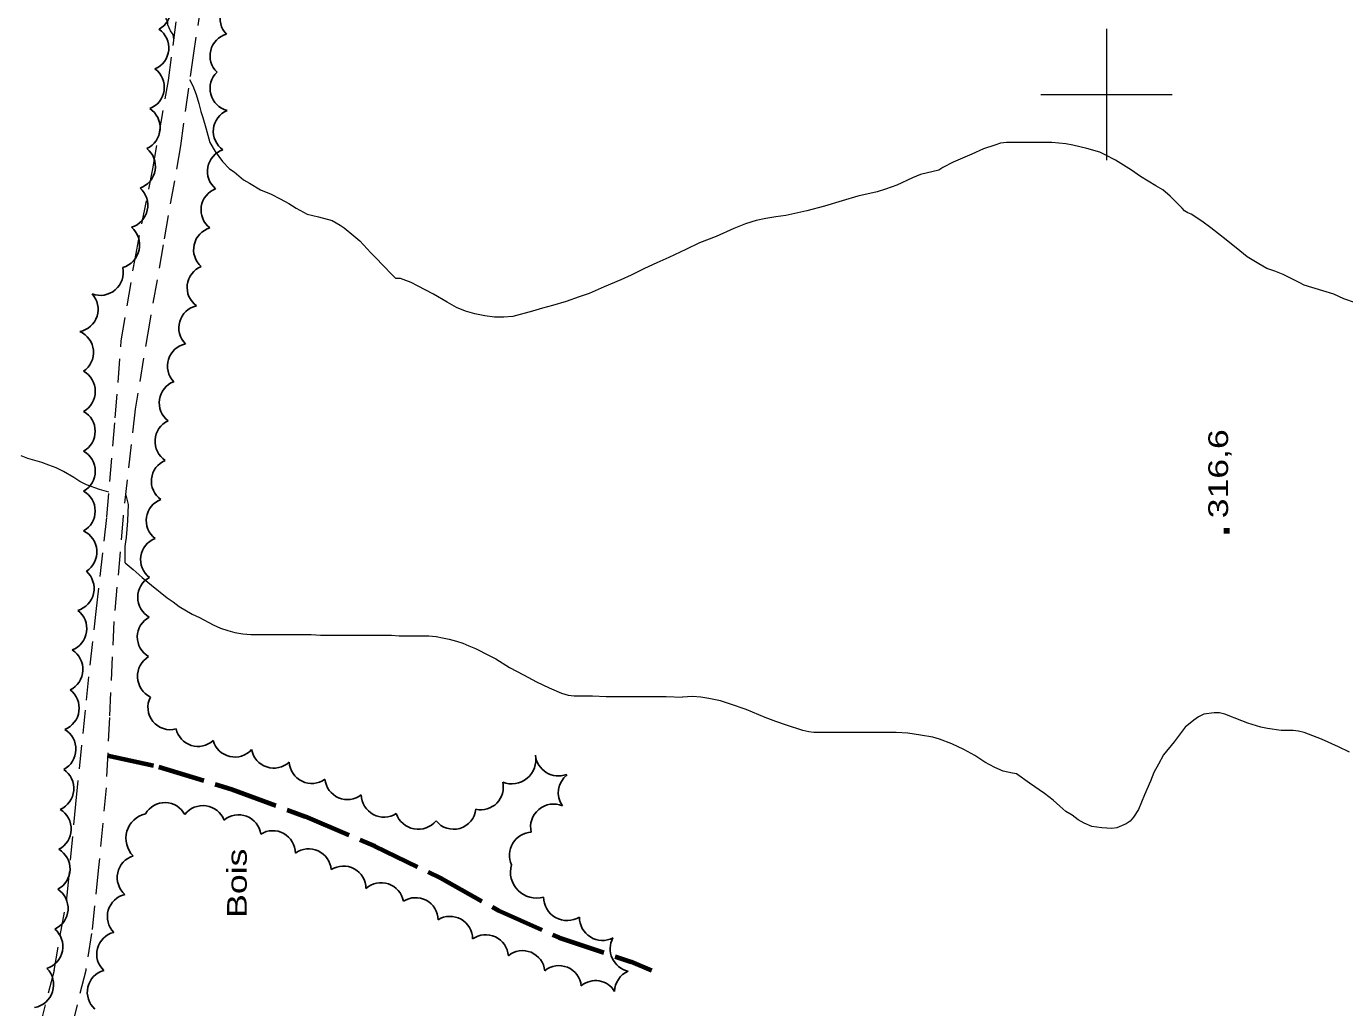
# Model space of a CAD drawing. Extents: x 240591 to 242335, y 5323482 to 5326937.
# Drawn here: x 240835.7 to 241036.2, y 5324261 to 5324410.4 of the extents above; entities that cross this region are included whole.
import ezdxf

# ---------------------------------------------------------------- set-up
doc = ezdxf.new("R2010")
doc.units = 0
doc.header["$LTSCALE"] = 1.2
doc.linetypes.add('LONG_DASHED', pattern=[7.5, 6, -1.5])
doc.linetypes.add('MEDIUM_DASHED', pattern=[4.5, 3, -1.5])
for name, color, linetype, lineweight in [('19', 7, 'Continuous', 13), ('2', 7, 'Continuous', 13), ('22', 7, 'LONG_DASHED', 70), ('3', 7, 'Continuous', 140), ('44', 7, 'Continuous', 25), ('61', 7, 'Continuous', 13)]:
    doc.layers.add(name, color=color, linetype=linetype, lineweight=lineweight)

msp = doc.modelspace()

# ---------------------------------------------------------------- linework, layer by layer
at = {"layer": '19', "linetype": 'MEDIUM_DASHED'}
for points in [[(240863.1, 5324419.4), (240861.1, 5324406.3), (240859.1, 5324392.2), (240856.5, 5324377.1), (240854.4, 5324365.2), (240852.2, 5324352.1), (240850.4, 5324335.8), (240849, 5324319.8), (240848.3, 5324305.2), (240847.8, 5324294.5), (240846.6, 5324281.9), (240845.6, 5324272.3), (240844.7, 5324266.7)], [(240839.9, 5324266.7), (240841.9, 5324278.1), (240843.2, 5324292), (240844.8, 5324307.8), (240846.3, 5324321.3), (240847.9, 5324335.7), (240849.2, 5324350.8), (240850.1, 5324362.5), (240852.2, 5324375), (240854.9, 5324388.7), (240857.3, 5324402.1), (240859.2, 5324416.9)], [(240839.9, 5324266.7), (240835.6, 5324250.1), (240830.7, 5324233.1), (240825.3, 5324215.3), (240819.4, 5324197.9), (240814.4, 5324181.3), (240809.9, 5324167.7), (240807.2, 5324159.7), (240806.2, 5324153.6), (240799.6, 5324150.5), (240789.6, 5324140.4), (240781.9, 5324131), (240772.8, 5324120.8), (240762.9, 5324110.8)], [(240844.7, 5324266.7), (240842.2, 5324256.7), (240839.1, 5324248.6), (240835.3, 5324236.2), (240830.5, 5324219.5), (240824.6, 5324201.3), (240820.2, 5324186.8), (240816.1, 5324172.5)]]:
    msp.add_lwpolyline(points, dxfattribs=at)
at = {"layer": '2'}
for points in [[(240858.1, 5324408.4), (240858, 5324409.1), (240857.6, 5324409.7), (240857.2, 5324410.6), (240857.2, 5324411.1), (240856.9, 5324411.6)], [(240848.2, 5324339.5), (240846.8, 5324339.9), (240844.8, 5324340.6), (240843.8, 5324341.1), (240842.9, 5324341.7), (240841.3, 5324342.6), (240840.2, 5324343.2), (240839.1, 5324343.6), (240838, 5324344), (240835.9, 5324344.6)], [(240850.7, 5324328.7), (240850.7, 5324331.2), (240850.8, 5324331.9), (240850.9, 5324332.6), (240851.1, 5324335.1), (240851.2, 5324337.6), (240850.8, 5324339.2)]]:
    msp.add_lwpolyline(points, dxfattribs=at)
at = {"layer": '2', "linetype": 'LONG_DASHED'}
for points in [[(240860.5, 5324402.3), (240861, 5324401.3), (240861.5, 5324400), (240861.9, 5324398.6), (240862.2, 5324397.4), (240862.5, 5324396.5), (240863, 5324394.9), (240863.3, 5324393.8), (240863.6, 5324392.7), (240864.4, 5324391.3), (240865.5, 5324389.8), (240866.6, 5324388.7), (240867.3, 5324388.2), (240868.7, 5324387), (240869.6, 5324386.5), (240871.3, 5324385.5), (240872.9, 5324384.8), (240874.3, 5324384.1), (240875.6, 5324383.4), (240876.7, 5324382.7), (240878.4, 5324381.8), (240880.1, 5324381.4), (240882.2, 5324380.8), (240883.4, 5324380.1), (240884, 5324379.7), (240885.5, 5324378.5), (240886.4, 5324377.7), (240888.1, 5324375.9), (240889, 5324375), (240889.8, 5324374.1), (240891.5, 5324372.4), (240891.9, 5324372)], [(240991.7, 5324392.7), (240990.7, 5324392.7), (240988, 5324392.7), (240984.8, 5324392.7), (240983.9, 5324392.6), (240983, 5324392.3), (240981.3, 5324391.7), (240979.5, 5324390.9), (240976.7, 5324389.7), (240975.1, 5324388.9), (240974.5, 5324388.5)], [(241037.9, 5324368.3), (241036.1, 5324368.9), (241034.6, 5324369.6), (241032.9, 5324370.1), (241030.1, 5324371), (241029.3, 5324371.4), (241026.9, 5324372.6), (241025.6, 5324373.1), (241024.4, 5324373.5), (241023.2, 5324374.2), (241021.4, 5324375.3), (241020.3, 5324376.2), (241018.2, 5324377.9), (241015.9, 5324379.7), (241014.5, 5324380.7), (241012.9, 5324381.8), (241012.4, 5324382), (241011.9, 5324382.3), (241011.5, 5324382.7), (241009.7, 5324384.5), (241008.6, 5324385.5), (241007.5, 5324386.1), (241005.2, 5324387.5), (241003.8, 5324388.5), (241001.4, 5324390), (240999.8, 5324390.8), (240999, 5324391.2), (240997, 5324391.8), (240994.9, 5324392.3), (240993.8, 5324392.5), (240991.7, 5324392.7)], [(240974.5, 5324388.5), (240971.7, 5324387.8), (240970.5, 5324387.3), (240968.1, 5324386.2), (240966.4, 5324385.6), (240965.1, 5324385.2), (240962.2, 5324384.5), (240959.8, 5324383.8), (240957.1, 5324383), (240954.4, 5324382.3), (240951.2, 5324381.6), (240949.7, 5324381.4), (240948.2, 5324381.1), (240946.7, 5324380.8), (240945.1, 5324380.3), (240943.3, 5324379.6), (240940.6, 5324378.4), (240938.1, 5324377.4), (240936, 5324376.4), (240933.4, 5324375.2), (240931.6, 5324374.4), (240929.7, 5324373.5), (240927.7, 5324372.5), (240926.1, 5324371.8), (240923.6, 5324370.7), (240921.3, 5324369.7), (240919.8, 5324369.2), (240917.8, 5324368.5), (240915.7, 5324367.9), (240914.2, 5324367.5), (240912.7, 5324367), (240909.7, 5324366.2), (240908.3, 5324366.1), (240906.9, 5324366.1), (240905.4, 5324366.3), (240903.9, 5324366.6), (240902.5, 5324367), (240901.1, 5324367.6), (240899.7, 5324368.4), (240897.6, 5324369.6), (240895.2, 5324370.9), (240894.2, 5324371.4), (240892.6, 5324372), (240891.9, 5324372)], [(240835.9, 5324344.6), (240834.9, 5324345)], [(240850.7, 5324328.7), (240850.7, 5324328.7), (240851.9, 5324327.7), (240853.3, 5324326.5), (240854.7, 5324325.3), (240857.1, 5324323.4), (240858, 5324322.8), (240858.9, 5324322.1), (240860.9, 5324320.9), (240862, 5324320.4), (240864.1, 5324319.3), (240865.2, 5324318.8), (240866.3, 5324318.4), (240867.4, 5324318.1), (240868.6, 5324317.9), (240869.8, 5324317.8), (240871, 5324317.8), (240872.3, 5324317.8), (240873.6, 5324317.8), (240874.9, 5324317.8), (240876.2, 5324317.8), (240877.6, 5324317.8), (240879, 5324317.8), (240880.4, 5324317.7), (240881.7, 5324317.7), (240883.1, 5324317.7), (240884.5, 5324317.7), (240885.8, 5324317.7), (240887.2, 5324317.7), (240888.5, 5324317.7), (240889.9, 5324317.7), (240891.2, 5324317.7), (240892.4, 5324317.6), (240894.8, 5324317.6), (240896.9, 5324317.6), (240898, 5324317.5), (240899, 5324317.3), (240900, 5324317.1), (240901.1, 5324316.8), (240902.1, 5324316.5), (240903, 5324316.1), (240904, 5324315.7), (240906.1, 5324314.6), (240907.1, 5324314.1), (240909.2, 5324312.8), (240911.3, 5324311.7), (240913.3, 5324310.6), (240915.2, 5324309.7), (240917.1, 5324308.9), (240918.1, 5324308.6), (240919, 5324308.5), (240920, 5324308.5), (240921.8, 5324308.5), (240923.9, 5324308.4), (240926.1, 5324308.4), (240928.3, 5324308.4), (240930.6, 5324308.4), (240933, 5324308.4), (240935.5, 5324308.3)], [(240948.1, 5324305.2), (240945.2, 5324306.4), (240942.8, 5324307.2), (240941.3, 5324307.7), (240939.5, 5324308.1), (240938.3, 5324308.3), (240937, 5324308.4), (240935.5, 5324308.3)], [(241037, 5324299.9), (241035.3, 5324300.7), (241032.7, 5324301.9), (241030.1, 5324302.9), (241029.2, 5324303.1), (241028.4, 5324303.2), (241026.6, 5324303.2), (241024.5, 5324303.5), (241023.5, 5324303.7), (241021.5, 5324304.3), (241020.6, 5324304.7), (241018, 5324305.7), (241017.2, 5324305.9), (241016.4, 5324305.9), (241014.8, 5324305.7), (241014, 5324305.3), (241013.3, 5324304.8), (241012, 5324303.7), (241011.5, 5324303.1), (241010.3, 5324301.5), (241008.7, 5324299.5), (241007.9, 5324298.1), (241007.2, 5324296.8), (241006.7, 5324295.5), (241005.8, 5324293.4), (241004.9, 5324291.2), (241004.1, 5324290), (241003.6, 5324289.4), (241003, 5324289), (241001.6, 5324288.4), (241000.8, 5324288.3), (240999.3, 5324288.4), (240997.8, 5324288.6), (240996.6, 5324289.1), (240995.7, 5324289.6), (240994.8, 5324290.3), (240993.8, 5324290.9), (240992.9, 5324291.7), (240991.9, 5324292.6), (240990.6, 5324293.6), (240988.3, 5324295.2), (240986.3, 5324296.6), (240985.7, 5324296.7), (240984.3, 5324297), (240983, 5324297.6), (240981.5, 5324298.4), (240980, 5324299.4), (240978.3, 5324300.3), (240976.5, 5324301.2), (240974.6, 5324301.9), (240973.6, 5324302.2), (240971.7, 5324302.5), (240969.8, 5324302.8), (240968, 5324302.9), (240966.3, 5324302.9), (240963.7, 5324302.9), (240960.9, 5324302.9), (240958.1, 5324302.9), (240955.5, 5324302.9), (240954.7, 5324303), (240953.8, 5324303.2), (240951.3, 5324304), (240949.7, 5324304.6), (240948.1, 5324305.2)]]:
    msp.add_lwpolyline(points, dxfattribs=at)
at = {"layer": '22'}
msp.add_lwpolyline([(240848, 5324299.4), (240855.8, 5324297.7), (240866.9, 5324294.3), (240878.1, 5324290.1), (240888.7, 5324285.6), (240898.7, 5324280.8), (240907.5, 5324275.8), (240916.7, 5324271.7), (240927.7, 5324268), (240930.8, 5324266.7)], dxfattribs=at)
at = {"layer": '3'}
msp.add_line((241018.3, 5324333.2), (241018.3, 5324334), dxfattribs=at)
at = {"layer": '44'}
for centre, radius, start, end in [((240868.579, 5324411.568), 3.442, 102.39736, 224.40467), ((240850.665, 5324383.142), 3.487, 286.58003, 48.40314), ((240865.692, 5324382.425), 3.449, 110.74721, 232.4546), ((240849.304, 5324377.086), 3.594, 287.08729, 49.0415), ((240864.562, 5324376.384), 3.446, 106.38921, 228.30568), ((240863.576, 5324370.616), 3.45, 112.23243, 233.84784), ((240846.899, 5324372.956), 3.53, 249.45507, 11.34474), ((240843.147, 5324367.303), 3.438, 281.11079, 43.04403), ((240862.309, 5324364.472), 3.444, 102.89401, 224.92787), ((240860.579, 5324358.67), 3.444, 101.88768, 223.71091), ((240859.323, 5324353.07), 3.448, 110.95228, 232.62604), ((240873.33, 5324300.931), 3.448, 190.5488, 312.52121), ((240856.756, 5324288.793), 3.437, 28.05396, 149.65451), ((240862.54, 5324288.341), 3.441, 21.09909, 143.04467), ((240890.076, 5324293.469), 3.446, 180.97719, 302.74351), ((240854.645, 5324286.799), 3.828, 102.90839, 224.61233), ((240895.284, 5324291.703), 3.53, 198.7212, 320.55283), ((240878.628, 5324281.771), 3.432, 4.32574, 126.21735), ((240883.905, 5324279.139), 3.435, 0.51743, 122.68747), ((240913.278, 5324281.663), 3.954, 163.89047, 285.87519), ((240889.644, 5324276.617), 3.439, 10.09912, 132.06703), ((240894.893, 5324274.342), 3.428, 1.13384, 122.91249), ((240917.939, 5324277.858), 3.579, 179.96578, 301.90723), ((240900.128, 5324271.493), 3.432, 359.78647, 121.78914), ((240905.568, 5324268.685), 3.441, 4.08244, 125.68788)]:
    msp.add_arc(centre, radius, start, end, dxfattribs=at)
for centre, major_axis, ratio, start_param, end_param in [((240854.257, 5324412.945), (3.395, -0.255), 0.998634, 5.2744232, 7.3946779), ((240853.864, 5324407.079), (3.414, -0.692), 0.999607, 5.3184188, 7.4472674), ((240867.012, 5324405.877), (-3.302, 0.821), 0.999637, 5.2210909, 7.3424952), ((240853.166, 5324401.082), (3.455, -0.446), 0.999865, 5.2153038, 7.3447029), ((240867.074, 5324400.907), (-3.43, -0.436), 0.999764, 5.3510118, 7.4749883), ((240852.531, 5324394.922), (3.479, -0.253), 0.999462, 5.2195848, 7.3472974), ((240867.585, 5324394.388), (-3.456, 0.323), 0.994743, 5.2122531, 7.3310861), ((240851.821, 5324389.038), (3.354, -0.957), 0.999694, 5.3290696, 7.456893), ((240866.662, 5324388.303), (-3.382, 0.64), 0.999978, 5.2191388, 7.3503449), ((240842.405, 5324360.748), (-2.028, 2.826), 0.999995, 3.1156854, 5.2450049), ((240842.656, 5324354.82), (3.494, 0), 0.999807, 5.2219133, 7.3444574), ((240842.646, 5324348.745), (3.493, -0.057), 0.993557, 5.2411666, 7.3573976), ((240858.691, 5324347.205), (-3.441, 0.244), 0.999978, 5.2203886, 7.3445376), ((240842.663, 5324342.68), (3.485, -0.132), 0.997946, 5.2585234, 7.3835755), ((240858.144, 5324341.15), (-3.435, 0.361), 0.995983, 5.2163648, 7.3392958), ((240842.632, 5324336.61), (3.508, -0.04), 0.992427, 5.2388613, 7.3502561), ((240857.364, 5324335.139), (-3.402, 0.581), 0.994506, 5.2434429, 7.3627639), ((240842.881, 5324330.388), (3.509, 0.252), 0.999995, 5.2175792, 7.3484699), ((240856.503, 5324329.229), (-3.426, 0.452), 0.993219, 5.2136984, 7.3297154), ((240842.476, 5324324.829), (3.332, -1.062), 0.999512, 5.3119892, 7.4356222), ((240856.076, 5324323.477), (-3.436, 0.46), 0.999765, 5.3503283, 7.4724751), ((240841.365, 5324318.706), (3.466, -0.47), 0.996361, 5.219824, 7.3388379), ((240855.995, 5324317.424), (-3.434, 0.283), 0.999133, 5.2856875, 7.4083378), ((240840.776, 5324312.512), (3.457, -0.476), 0.999402, 5.3043459, 7.4272134), ((240856.116, 5324311.448), (-3.494, 0.502), 0.99989, 5.4087946, 7.5337096), ((240840.21, 5324306.598), (3.459, -0.527), 0.994994, 5.2404595, 7.360543), ((240857.579, 5324306.739), (-2.888, -1.818), 0.999551, 5.2492978, 7.5522256), ((240839.725, 5324300.362), (3.485, -0.078), 0.999222, 5.219787, 7.3420655), ((240861.792, 5324304.207), (3.408, -0.317), 0.999793, 3.4584441, 5.5411214), ((240867.394, 5324302.602), (3.277, 1.023), 0.999995, 3.1138248, 5.245436), ((240879.102, 5324298.59), (-1.737, -2.98), 0.999391, 5.2979987, 7.4292811), ((240909.497, 5324298.785), (2.341, -2.856), 0.999995, 5.220307, 7.348353), ((240916.618, 5324299.803), (3.24, -1.339), 0.999985, 3.6343093, 5.4606828), ((240839.396, 5324294.382), (3.484, -0.301), 0.999353, 5.2178182, 7.3472095), ((240884.525, 5324296.136), (-1.354, -3.166), 0.999994, 5.2200677, 7.3448174), ((240920.111, 5324293.716), (0.594, -3.457), 0.999626, 3.6432973, 5.1415932), ((240904.823, 5324294.55), (2.998, 1.63), 0.99933, 3.9904616, 6.0218314), ((240915.891, 5324288.521), (-3.091, -1.645), 0.999941, 3.8282602, 6.0237339), ((240839.017, 5324288.219), (3.478, -0.213), 0.996479, 5.2482635, 7.3712183), ((240867.951, 5324286.958), (1.399, 3.128), 0.998825, 5.2736571, 7.4024011), ((240900.677, 5324291.587), (3.354, 0.623), 0.999617, 3.631155, 5.9927514), ((240873.165, 5324284.529), (2.093, 2.725), 0.999828, 5.3703073, 7.4980628), ((240912.67, 5324284.221), (-2.114, -2.801), 0.999867, 3.8410039, 5.7882957), ((240838.824, 5324282.138), (3.473, -0.317), 0.999012, 5.2851557, 7.4071785), ((240852.931, 5324280.827), (-3.361, 0.723), 0.998911, 5.2225563, 7.3440037), ((240838.541, 5324276.137), (3.47, -0.242), 0.999865, 5.2150775, 7.3460101), ((240851.432, 5324274.9), (-3.301, 0.964), 0.999729, 5.2228291, 7.3483484), ((240923.336, 5324274.757), (3.059, -1.714), 0.999868, 3.6344302, 5.6940541), ((240837.751, 5324270.327), (3.412, -0.674), 0.999865, 5.2150775, 7.3460101), ((240849.782, 5324269.169), (-2.628, 2.164), 0.999892, 5.6360024, 7.7924148), ((240928.002, 5324269.991), (0.913, -3.381), 0.999766, 3.9584449, 5.7914265), ((240911.164, 5324266.302), (-3.149, 1.294), 0.999984, 3.6337332, 5.7910449), ((240916.714, 5324264.022), (-3.149, 1.294), 0.999984, 3.6337332, 5.7910449), ((240836.254, 5324264.528), (3.007, 1.906), 0.999313, 4.3370665, 6.4908186), ((240848.368, 5324263.377), (-0.767, -3.339), 0.999938, 3.6354391, 5.7893388), ((240928.643, 5324263.384), (-1.349, -3.232), 0.999766, 3.9584449, 5.072436), ((240922.264, 5324261.742), (-3.149, 1.294), 0.999984, 4.0763646, 5.7910449)]:
    msp.add_ellipse(centre, major_axis=major_axis, ratio=ratio, start_param=start_param, end_param=end_param, dxfattribs=at)
at = {"layer": '61'}
for points in [[(241000, 5324410), (241000, 5324400), (241000, 5324390)], [(240990, 5324400), (241000, 5324400), (241010, 5324400)]]:
    msp.add_lwpolyline(points, dxfattribs=at)

# ---------------------------------------------------------------- texts
at = {"layer": '3', "width": 1.35}
msp.add_text('316,6', height=3, rotation=90, dxfattribs=at).set_placement((241018.5, 5324335.5))
at = {"layer": '44', "width": 1.35}
msp.add_text('Bois', height=3, rotation=90, dxfattribs=at).set_placement((240869.2, 5324274.7))

doc.saveas('drawing.dxf')
